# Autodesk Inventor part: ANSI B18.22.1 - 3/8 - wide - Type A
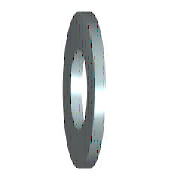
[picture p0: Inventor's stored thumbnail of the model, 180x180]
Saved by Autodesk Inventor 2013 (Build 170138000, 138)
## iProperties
IsCustomPart: 0
Created: 2008-02
Part Number: ANSI B18.22.1 - 3/8 - wide - Type A
Material: Steel, Mild
Description: Plain Washer (Inch )Type A and B
Document SubType Name: Modeling
Standard: ANSI B18.22.1
Designer: ssc
Standard Revision: 1998
Standards Organization: ANSI
Language: en-US
Size Designation: 3/8 - wide - Type A
Categories: <MemberInstance><Categories><Category DisplayName="Fasteners" InternalName="e4da775c-781d-43d5-af7c-5136215cf5a6" Mnemonic="FSTN"><Category DisplayName="Washers
Density: 1 g/cm^3
Author: ssc
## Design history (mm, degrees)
sketch "Sketch"
  geometry: C1 r 12.7 at (0, 0); C2 r 5.563 at (0, 0); 1 further point
  constraints: 2 centre point, 2 coincident
  dimensions: "d0" = 11.1252 diameter of C2 (= SD1); "d1" = 25.4 diameter of C1 (= SD2)
extrude "Body" new body sketch "Sketch" distance "d2" = 2.1082 (= SD); taper "d3" = 0 deg
workaxis "Work Axis1"
workplane "Work Plane1"
body "Solid1"
other parameters: "SD1" = 11.1252 [user parameter; used in 1 equation term], "SD2" = 25.4 [user parameter; used in 1 equation term], "SD" = 2.1082 [user parameter; used in 1 equation term], "d4" = 0, "d5" = 0, "d6" = 0, "d7" = 0, "NND" = 9.525 [user parameter]
